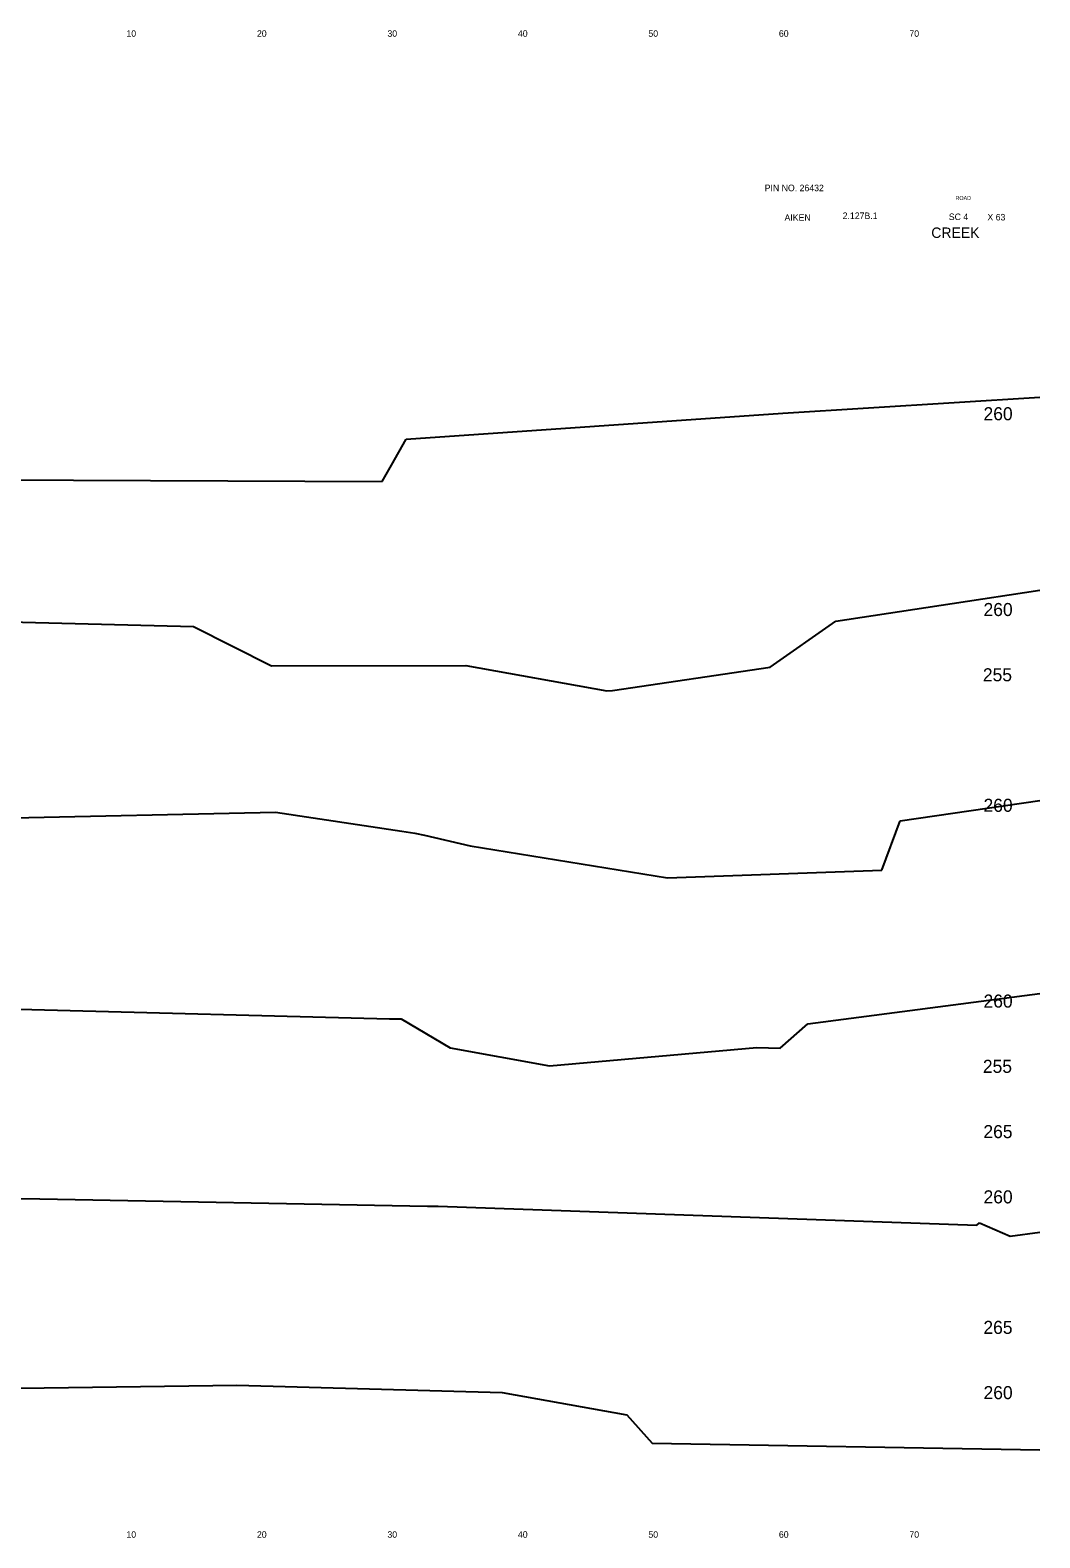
# Model space of a CAD drawing. Extents: x 175484 to 175644, y 176972 to 177478.
# Drawn here: x 175566.8 to 175644.1, y 176972.3 to 177087.8 of the extents above; entities that cross this region are included whole.
import ezdxf

# ---------------------------------------------------------------- set-up
doc = ezdxf.new("R2010")
doc.units = 0
for name, color, linetype in [('Level 1', 7, 'Continuous'), ('Level 2', 7, 'Continuous'), ('Level 3', 7, 'Continuous'), ('Level 60', 7, 'Continuous')]:
    doc.layers.add(name, color=color, linetype=linetype)

msp = doc.modelspace()

# ---------------------------------------------------------------- linework, layer by layer
at = {"layer": 'Level 60'}
for p, q in [((175624.43, 177058.46), (175644.13, 177059.68)), ((175595.57, 177056.46), (175624.43, 177058.46)), ((175594.43, 177054.49), (175595.57, 177056.46)), ((175593.72, 177053.22), (175594.43, 177054.49)), ((175564.13, 177053.36), (175593.72, 177053.22)), ((175637.41, 177043.88), (175644.13, 177044.89)), ((175628.5, 177042.54), (175637.41, 177043.88)), ((175564.13, 177042.51), (175579.26, 177042.12)), ((175623.45, 177039), (175628.5, 177042.54)), ((175579.26, 177042.12), (175585.24, 177039.11)), ((175585.24, 177039.11), (175600.14, 177039.14)), ((175600.14, 177039.14), (175610.94, 177037.18)), ((175611.39, 177037.21), (175623.45, 177039)), ((175610.94, 177037.18), (175611.39, 177037.21)), ((175633.41, 177027.23), (175644.13, 177028.79)), ((175564.26, 177027.43), (175585.56, 177027.9)), ((175585.56, 177027.9), (175595.23, 177026.44)), ((175632.03, 177023.44), (175633.41, 177027.23)), ((175595.23, 177026.44), (175596.22, 177026.29)), ((175596.22, 177026.29), (175596.96, 177026.12)), ((175596.96, 177026.12), (175600.48, 177025.32)), ((175600.48, 177025.32), (175615.58, 177022.85)), ((175615.58, 177022.85), (175632.03, 177023.44)), ((175626.34, 177011.67), (175644.13, 177014.01)), ((175564.18, 177012.84), (175566.89, 177012.77)), ((175566.89, 177012.77), (175594.29, 177012.07)), ((175594.29, 177012.07), (175595.17, 177012.05)), ((175595.17, 177012.05), (175598.95, 177009.85)), ((175624.22, 177009.8), (175626.34, 177011.67)), ((175598.95, 177009.85), (175606.56, 177008.45)), ((175606.56, 177008.45), (175622.44, 177009.86)), ((175622.44, 177009.86), (175624.22, 177009.8)), ((175564.25, 176998.32), (175567.48, 176998.27)), ((175567.48, 176998.27), (175597.2, 176997.71)), ((175597.2, 176997.71), (175598.01, 176997.71)), ((175598.01, 176997.71), (175639.29, 176996.24)), ((175639.29, 176996.24), (175639.5, 176996.43)), ((175639.5, 176996.43), (175641.84, 176995.42)), ((175641.84, 176995.42), (175644.13, 176995.72)), ((175564.13, 176983.74), (175582.58, 176984)), ((175582.58, 176984), (175602.91, 176983.43)), ((175602.91, 176983.43), (175612.48, 176981.73)), ((175612.48, 176981.73), (175614.41, 176979.56)), ((175614.41, 176979.56), (175644.13, 176979.05))]:
    msp.add_line(p, q, dxfattribs=at)

# ---------------------------------------------------------------- texts
at = {"layer": 'Level 1'}
for s, height, p in [('PIN NO. 26432', 0.5, (175623.04, 177075.47)), ('ROAD', 0.3, (175637.66, 177074.8)), ('AIKEN', 0.5, (175624.56, 177073.2)), (' 2.127B.1', 0.5, (175628.83, 177073.34)), ('SC 4', 0.5, (175637.15, 177073.26)), ('X 63', 0.5, (175640.11, 177073.23)), ('CREEK', 0.8, (175635.81, 177071.89))]:
    msp.add_text(s, height=height, dxfattribs=at).set_placement(p)
at = {"layer": 'Level 2'}
for s, p in [('10', (175574.13, 177087.3)), ('20', (175584.13, 177087.3)), ('30', (175594.13, 177087.3)), ('40', (175604.13, 177087.3)), ('50', (175614.13, 177087.3)), ('60', (175624.13, 177087.3)), ('70', (175634.13, 177087.3)), ('10', (175574.13, 176972.3)), ('20', (175584.13, 176972.3)), ('30', (175594.13, 176972.3)), ('40', (175604.13, 176972.3)), ('50', (175614.13, 176972.3)), ('60', (175624.13, 176972.3)), ('70', (175634.13, 176972.3))]:
    msp.add_text(s, height=0.5, dxfattribs=at).set_placement(p)
at = {"layer": 'Level 3'}
for s, p in [(' 260', (175639.44, 177057.92)), (' 260', (175639.44, 177042.92)), (' 255', (175639.39, 177037.92)), (' 260', (175639.44, 177027.92)), (' 260', (175639.44, 177012.92)), (' 255', (175639.39, 177007.92)), (' 265', (175639.43, 177002.92)), (' 260', (175639.44, 176997.92)), (' 265', (175639.43, 176987.92)), (' 260', (175639.44, 176982.92))]:
    msp.add_text(s, height=1, dxfattribs=at).set_placement(p)

doc.saveas('drawing.dxf')
